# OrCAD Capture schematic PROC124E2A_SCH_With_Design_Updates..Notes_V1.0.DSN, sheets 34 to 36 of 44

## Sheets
34 33. MCU HEADER: size C; title: MCU HEADER
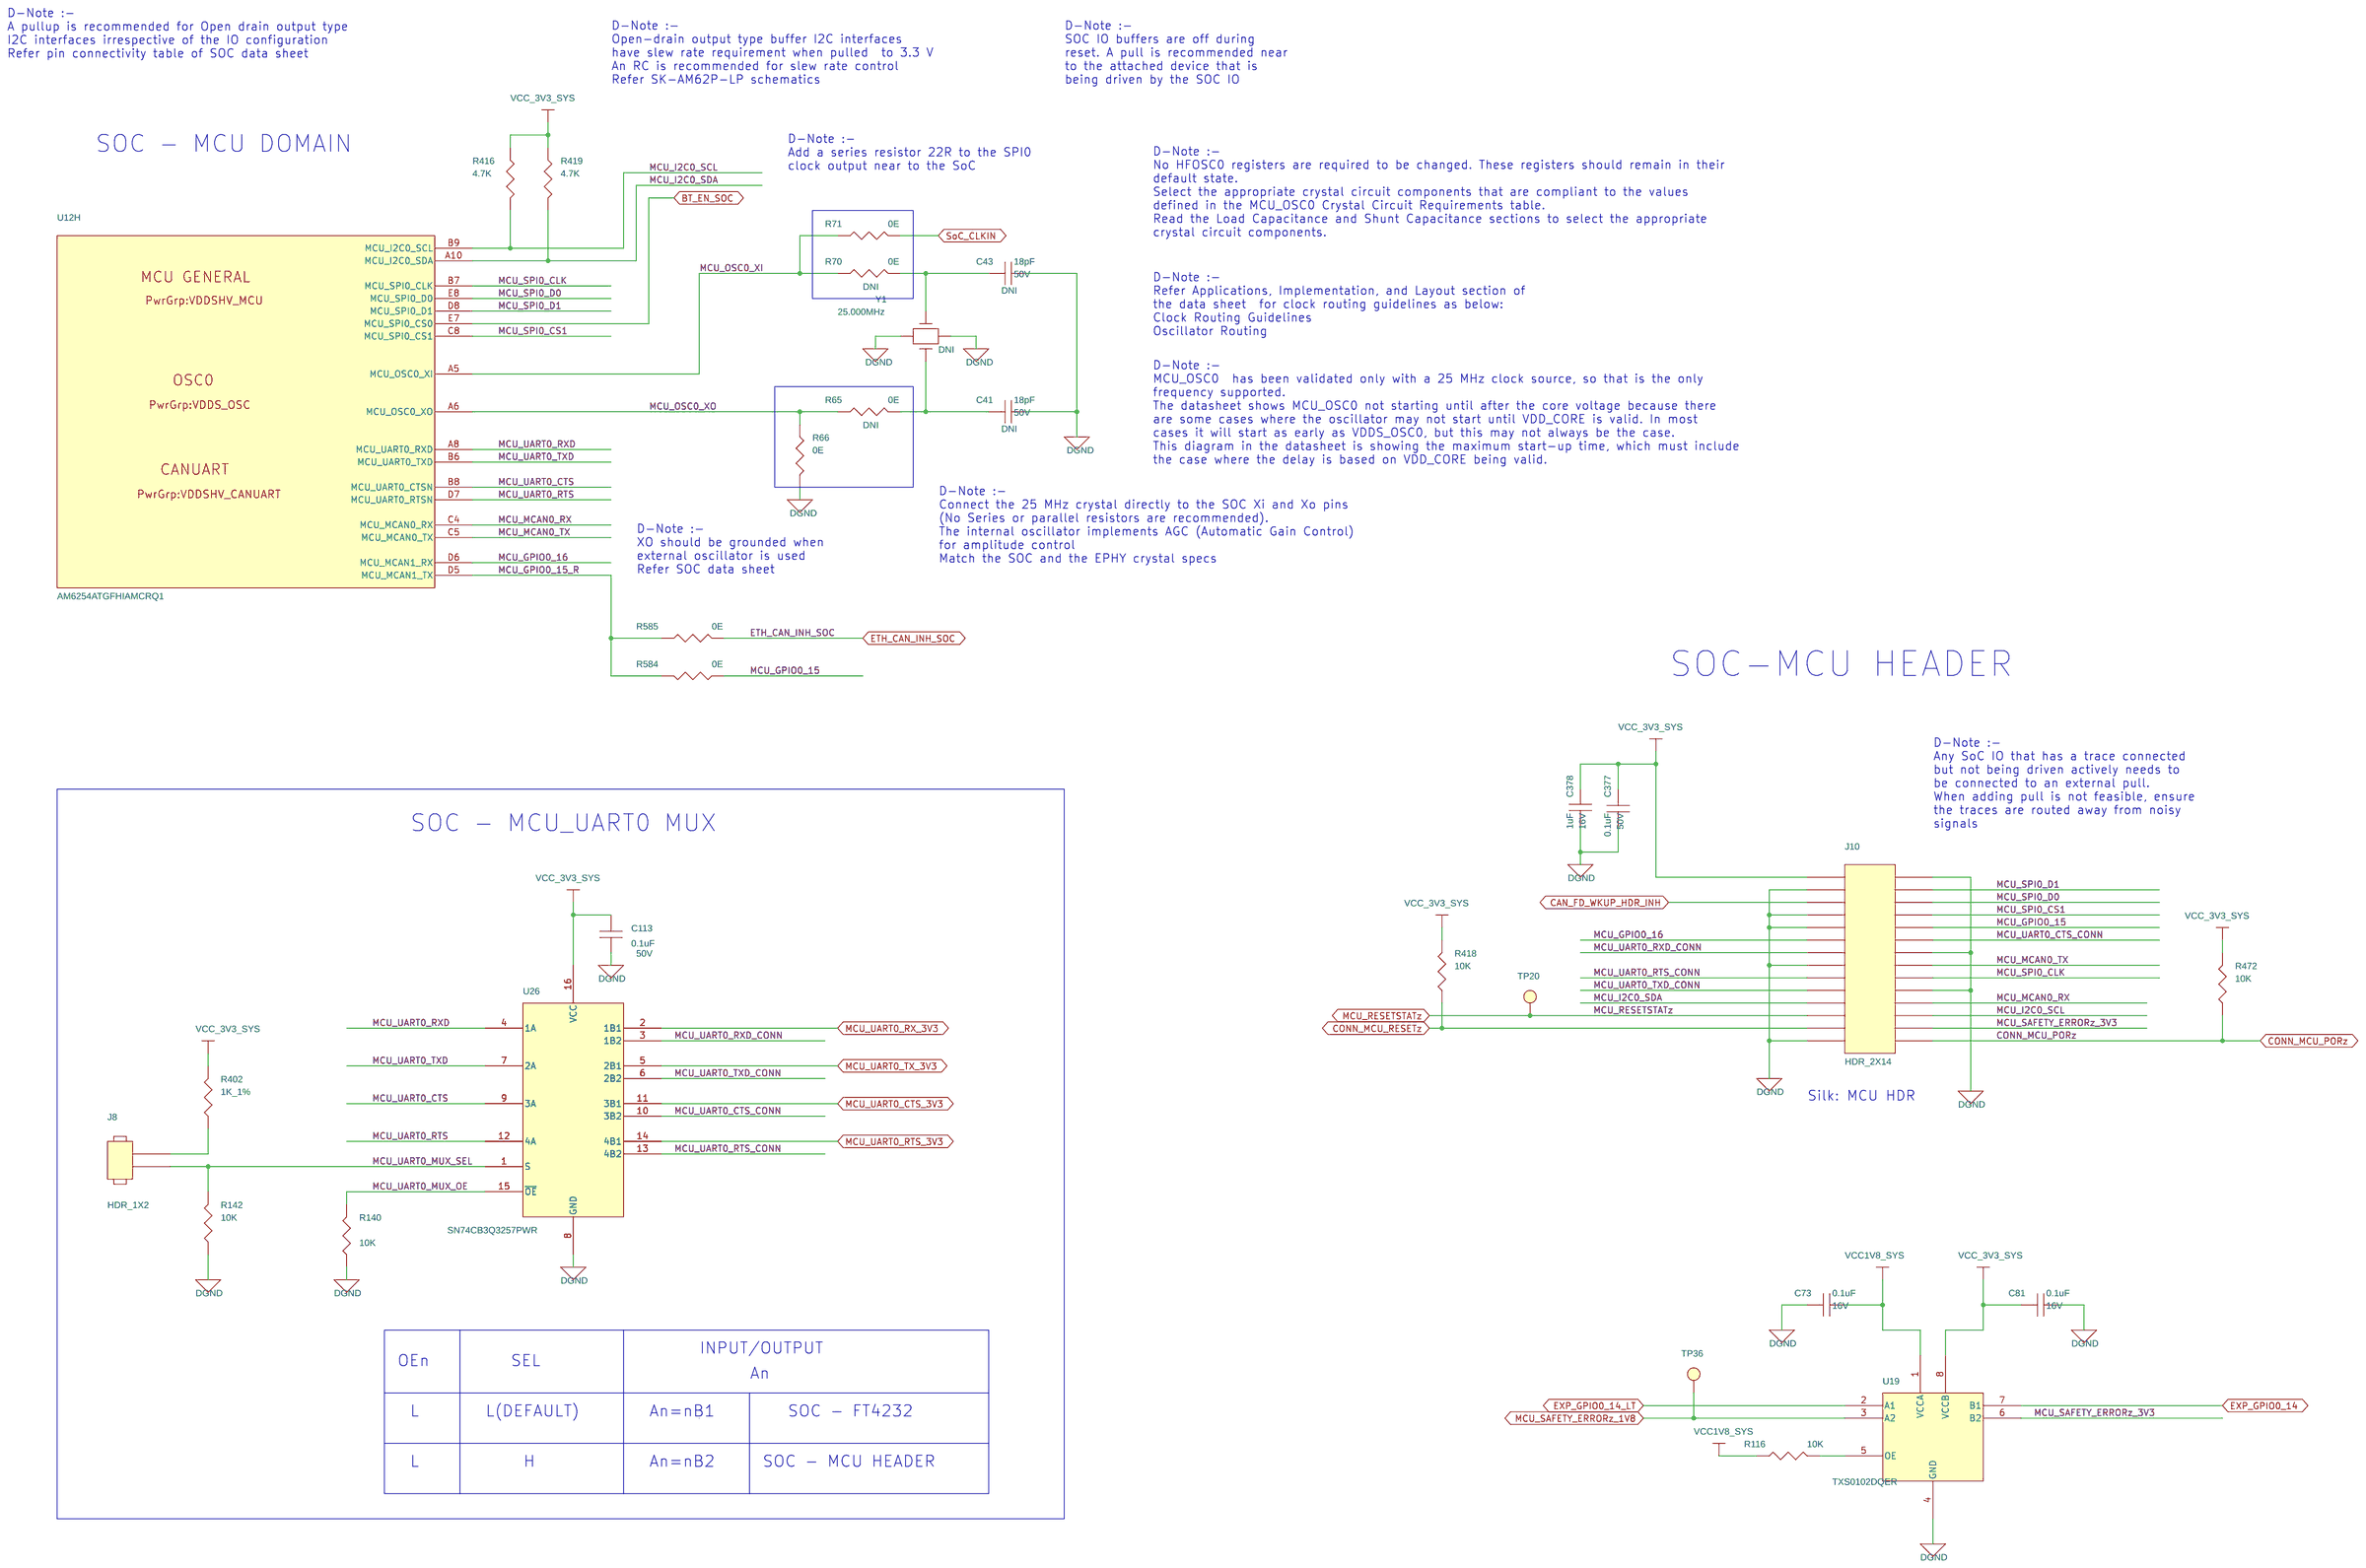
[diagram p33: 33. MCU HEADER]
35 34. USB 2.0 TYPE-A: size B; title: USB 2.0 TYPE-A
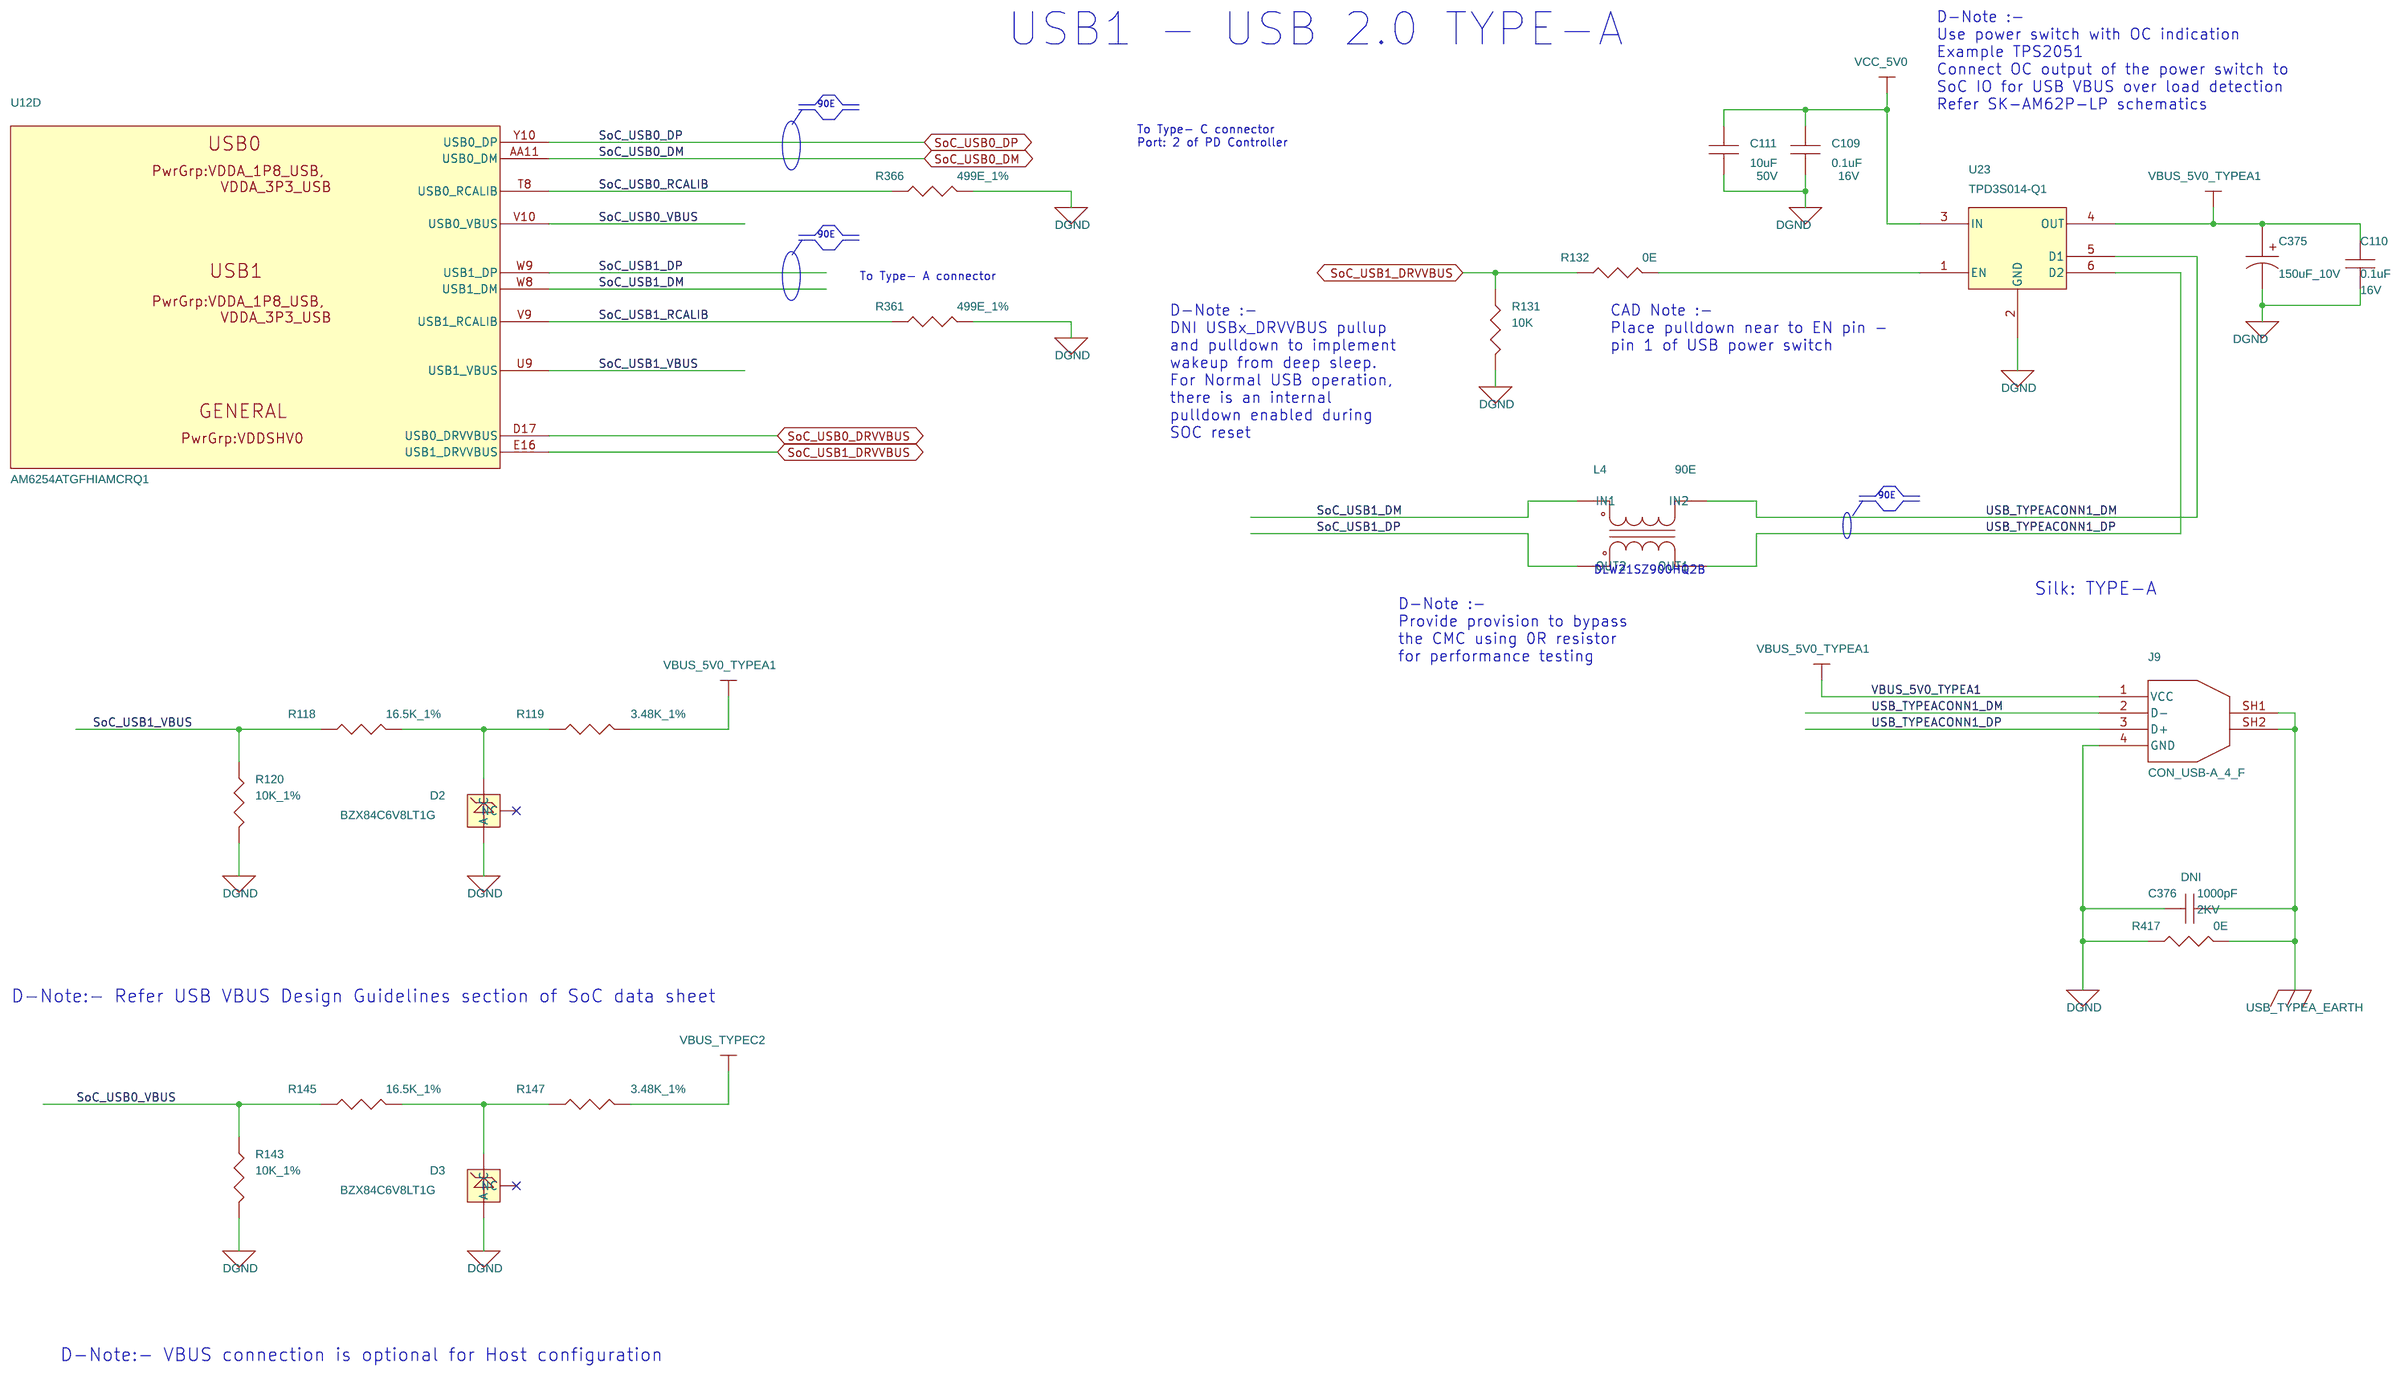
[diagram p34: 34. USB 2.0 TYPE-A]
36 35. USB 2.0 TYPE-C DRP: size C; title: USB TYPE-C DRP
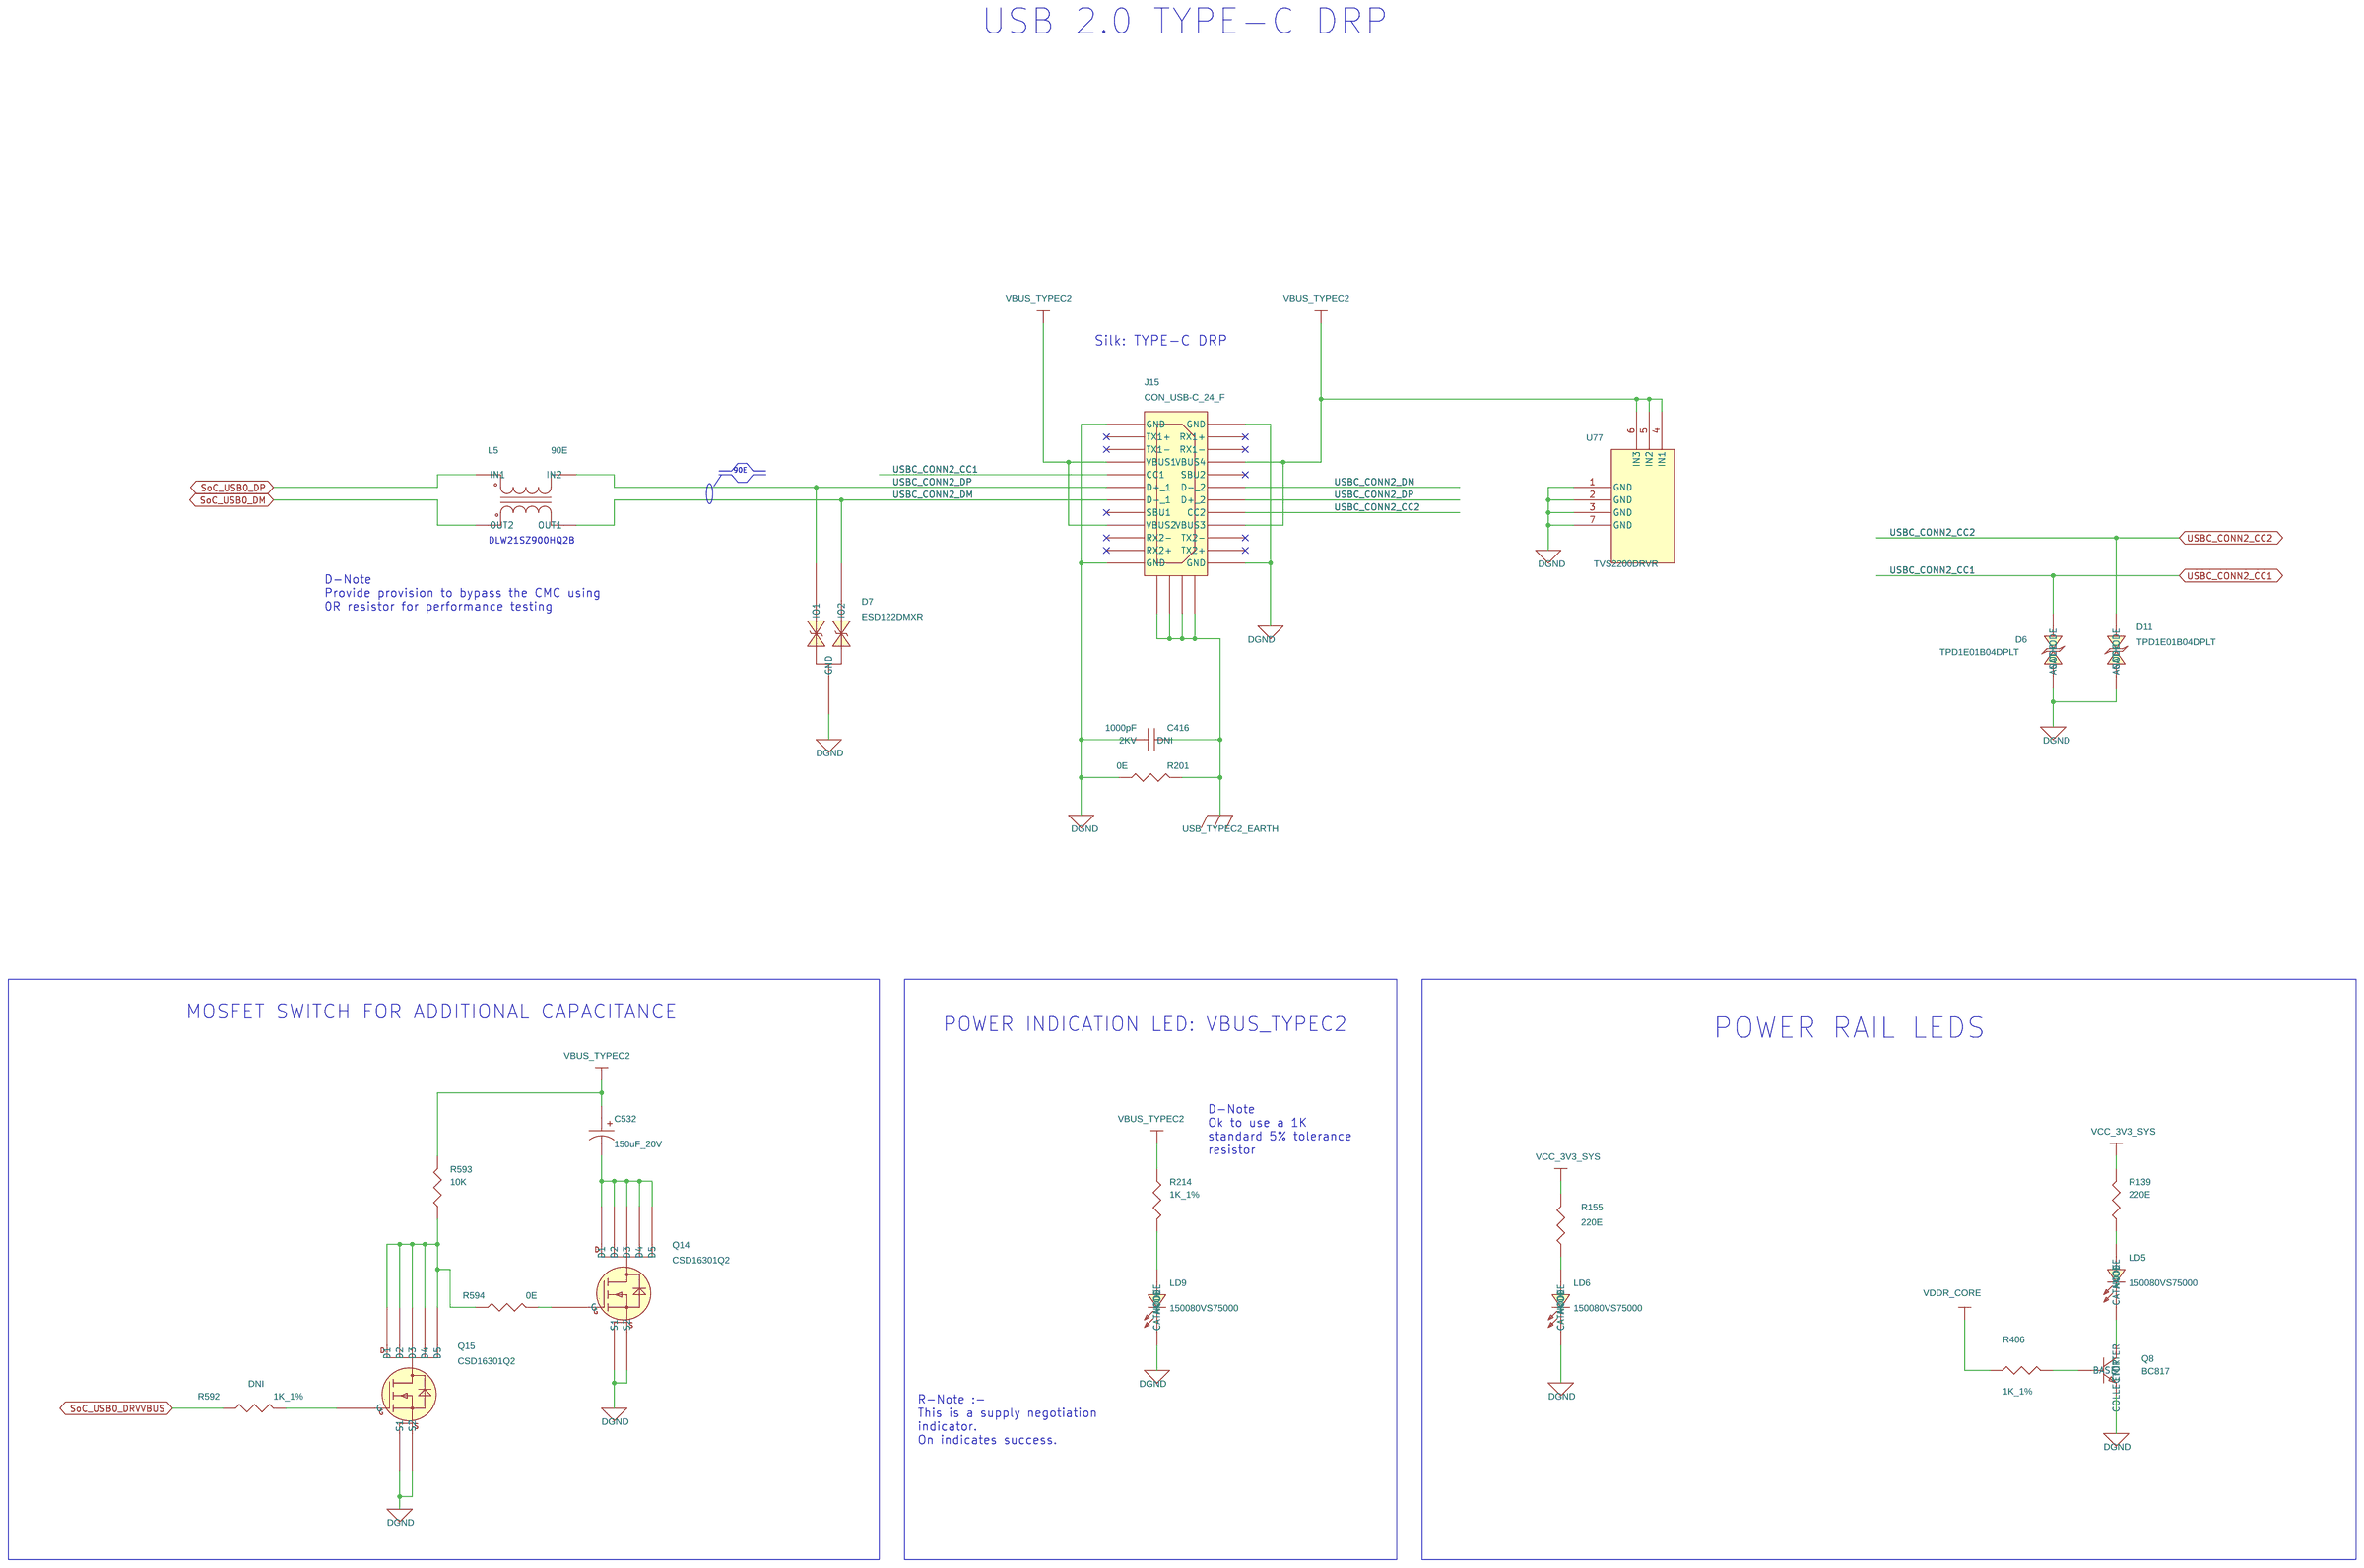
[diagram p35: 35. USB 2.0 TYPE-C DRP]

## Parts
sheet 15. SOC POWER CAPS
U12  AM6254ATGFHIAMCRQ1  [FCBGA441_31-49_680X680_2-6]  (sections A,B,C,D,E,F,G,H,I,J,K,L,M,N,O,P,Q,R)
sheet 33. MCU HEADER
C41  18pF  [CAP0402_0-75]
C43  18pF  [CAP0402_0-75]
C73  0.1uF  [CAP0201_0-5]
C81  0.1uF  [CAP0201_0-5]
C113  0.1uF  [CAP0402_0-75]
C377  0.1uF  [CAP0402_0-75]
C378  1uF  [CAP0201_0-5]
J8  HDR_1X2  [HDR_1X2_90120-0122_S_T_5-6]
J10  HDR_2X14  [HDR_14X2_100_S_T]
R65  0E  [RES0201_0-5]
R66  0E  [RES0201_0-5]
R70  0E  [RES0201_0-5]
R71  0E  [RES0201_0-5]
R116  10K  [RES0201_0-5]
R140  10K  [RES0201_0-5]
R142  10K  [RES0201_0-5]
R402  1K_1%  [RES0201_0-5]
R416  4.7K  [RES0201_0-5]
R418  10K  [RES0201_0-5]
R419  4.7K  [RES0201_0-5]
R472  10K  [RES0201_0-5]
R584  0E  [RES0201_0-5]
R585  0E  [RES0201_0-5]
TP20  TP20_SMD  [TP20_SMD]
TP36  TP20_SMD  [TP20_SMD]
U19  TXS0102DQER  [X2SON8_TXS0102_40X60_0-4]
U26  SN74CB3Q3257PWR  [TSSOP16_25-59_205X180]
Y1  25.000MHz  [XTAL4_XRCGB-FM_80X60_SMD_0-7]
sheet 34. USB 2.0 TYPE-A
C109  0.1uF  [CAP0201_0-5]
C110  0.1uF  [CAP0201_0-5]
C111  10uF  [CAP0805_1-5]
C375  150uF_10V  [CAPT7343D_3-25]
C376  1000pF  [CAP1206_1-75]
D2  BZX84C6V8LT1G  [SOT23-123_1-2]
D3  BZX84C6V8LT1G  [SOT23-123_1-2]
J9  CON_USB-A_4_F  [CON_USBA4_629104151_S_R_S_7-4]
L4  90E  [IND4_DLW21H_90X60_SMD_1-4]
R118  16.5K_1%  [RES0402_0-5]
R119  3.48K_1%  [RES0201_0-5]
R120  10K_1%  [RES0201_0-5]
R131  10K  [RES0201_0-5]
R132  0E  [RES0201_0-5]
R143  10K_1%  [RES0201_0-5]
R145  16.5K_1%  [RES0402_0-5]
R147  3.48K_1%  [RES0201_0-5]
R361  499E_1%  [RES0402_0-5]
R366  499E_1%  [RES0402_0-5]
R417  0E  [RES0603_0-75]
U23  TPD3S014-Q1  [SOT23-6_1-5]
sheet 35. USB 2.0 TYPE-C DRP
C416  1000pF  [CAP1206_1-75]
C532  150uF_20V  [CAPT7343X_4-3]
D6  TPD1E01B04DPLT  [DIO_DFN0201_0-4]
D7  ESD122DMXR  [X2SON3_ESD122DMX_30X40_0-4]
D11  TPD1E01B04DPLT  [DIO_DFN0201_0-4]
J15  CON_USB-C_24_F  [CON_USBC24_2012670_S_R_S_3-9]
L5  90E  [IND4_DLW21H_90X60_SMD_1-4]
LD5  150080VS75000  [LED_150080VS75000_80X50_SMD_0-8]
LD6  150080VS75000  [LED_150080VS75000_80X50_SMD_0-8]
LD9  150080VS75000  [LED_150080VS75000_80X50_SMD_0-8]
Q8  BC817  [TO_SOT23-123]
Q14  CSD16301Q2  [WSON6_CSD13202Q2_80X80_0-8]
Q15  CSD16301Q2  [WSON6_CSD13202Q2_80X80_0-8]
R139  220E  [RES0402_0-5]
R155  220E  [RES0402_0-5]
R201  0E  [RES0603_0-75]
R214  1K_1%  [RES0402_0-5]
R406  1K_1%  [RES0402_0-5]
R592  1K_1%  [RES0201_0-5]
R593  10K  [RES0201_0-5]
R594  0E  [RES0201_0-5]
U77  TVS2200DRVR  [SON6_25-59_85X85_0-8]

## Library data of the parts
U12 = AM6254ATGFHIAMCRQ1_FCBGA441: IC AM62Q SoC MICROPROCESSOR FCBGA441; Chkd/date: PRADEEP/180324; Crtd /date: TAMILARASU/180324; Custom_Duty: 15%; Customs_HS_Code: 85423100; Distributor_name: NA; Distributor_part_number: NA; Footprint Path: Y:\MIS_DATABASE\Library\ALTIUM_TOOL\PCB_FOOTPRINTS\Altium_Footprint_Lib.PcbLib; Height: 2.57MM; Library Path: Y:\MIS_DATABASE\Library\ALTIUM_TOOL\SCHEMATICS_PARTS\MS_MICROPROCESSOR_Library.schlib; Mfr_name: TEXAS INSTRUMENTS; Mistral Part No: 141224030001-R; Package: FCBGA441; Part_type: ICS\DIGITAL\MICROPROCESSOR; Project: TI_AM62Q_BRD; RoHS: NA; Temperature: NA; Tolerance: NA; Voltage: NA; Wattage: NA; Weight: NA; Datasheet: Y:\MIS_DATABASE\DATASHEETS\ICS\DIGITAL\MICROCONTROLLER\AM62Q-SoC.PDF
C41 C43 = CAP: CAP CERAMIC 18pF 50V 5% HI-Q C0G(NP0) 0402; Assembly_Instruction: DNI; Chkd/date: VASANTHA/030315; Crtd /date: NAVEED/271014; Custom_Duty: 15%; Customs_HS_Code: 85322990; Distributor_name: DIGIKEY; Distributor_part_number: 490-3119-1-ND; Footprint Path: Y:\MIS_DATABASE\Library\ALTIUM_TOOL\PCB_FOOTPRINTS\Altium_Footprint_Lib.PcbLib; Height: 0.55MM; Library Path: Y:\MIS_DATABASE\Library\ALTIUM_TOOL\SCHEMATICS_PARTS\MS_DISCRETE_Library.schlib; Mfr_name: MURATA; Mfr_part_number: GJM1555C1H180JB01D; Mistral Part No: 120014100019-R; Package: 0402; Part_type: CAPACITORS\CERAMIC; Project: DC_MIST_RDC; RoHS: RoHS; Temperature: -55°C+125°C; Tolerance: 5%; Voltage: 50V; Wattage: NA; Weight: 6mg; Datasheet: Y:\MIS_DATABASE\DATASHEETS\CAPACITORS\MURATA-GXX-SER_NOV17.PDF
C73 C81 = CAP: CAP CERAMIC 0.1uF 16V 10% X5R 0201; Alt_Mfr_name: YAGEO AMERICA; Alt_Mfr_part_number: CC0402KRX5R8BB104; Chkd/date: MANIRAJA/230118; Crtd /date: MANIRAJA/230118; Custom_Duty: 15%; Customs_HS_Code: 85322990; Distributor_name: DIGIKEY; Distributor_part_number: 490-14305-1-ND; Footprint Path: Y:\MIS_DATABASE\Library\ALTIUM_TOOL\PCB_FOOTPRINTS\Altium_Footprint_Lib.PcbLib; Height: 0.33MM; Library Path: Y:\MIS_DATABASE\Library\ALTIUM_TOOL\SCHEMATICS_PARTS\MS_DISCRETE_Library.schlib; Mfr_name: MURATA; Mfr_part_number: GRM033R61C104KE14D; Mistral Part No: 120009030072-R; Package: 0201; Part_type: CAPACITORS\CERAMIC; Project: TI_MAXIE_CPB; RoHS: RoHS; Temperature: -55°C+85°C; Tolerance: 10%; Voltage: 16V; Wattage: NA; Weight: 0.33mg; Datasheet: Y:\MIS_DATABASE\DATASHEETS\CAPACITORS\GRM033R61C104KE14.PDF
C113 C377 = CAP: CAP CERAMIC 0.1uF 50V 10% X7R 0402; Alt_Mfr_name: YAGEO AMERICA; Alt_Mfr_part_number: CC0402KRX5R8BB104; Chkd/date: MANIRAJA/261020; Crtd /date: ALVY/211020; Custom_Duty: 15%; Customs_HS_Code: 85322990; Distributor_name: DIGIKEY; Distributor_part_number: 490-10700-1-ND; Footprint Path: Y:\MIS_DATABASE\Library\ALTIUM_TOOL\PCB_FOOTPRINTS\Altium_Footprint_Lib.PcbLib; Height: 0.55MM; Library Path: Y:\MIS_DATABASE\Library\ALTIUM_TOOL\SCHEMATICS_PARTS\MS_DISCRETE_Library.schlib; Mfr_name: MURATA; Mfr_part_number: GRM155R71H104KE14D; Mistral Part No: 120011100014-R; Package: 0402; Part_type: CAPACITORS\CERAMIC; Project: J7_CP; RoHS: RoHS; Temperature: -55°C+125°C; Tolerance: 10%; Voltage: 50V; Wattage: NA; Weight: 3.1mg; Datasheet: Y:\MIS_DATABASE\DATASHEETS\CAPACITORS\GRM155R71H104KE14.PDF
C378 = CAP: CAP CERAMIC 1uF 16V 20% X5R 0201; Chkd/date: MANIRAJA/300520; Crtd /date: ALVY/260520; Custom_Duty: 15%; Customs_HS_Code: 85322990; Distributor_name: DIGIKEY; Distributor_part_number: 490-18654-1-ND; Footprint Path: Y:\MIS_DATABASE\Library\ALTIUM_TOOL\PCB_FOOTPRINTS\Altium_Footprint_Lib.PcbLib; Height: 0.39MM; Library Path: Y:\MIS_DATABASE\Library\ALTIUM_TOOL\SCHEMATICS_PARTS\MS_DISCRETE_Library.schlib; Mfr_name: MURATA; Mfr_part_number: GRM033R61C105ME15D; Mistral Part No: 120018090038-R; Package: 0201; Part_type: CAPACITORS\CERAMIC; Project: QCS610_NANOSOM; RoHS: RoHS; Temperature: -55°C+85°C; Tolerance: 20%; Voltage: 16V; Wattage: NA; Weight: 0.33mg; Datasheet: Y:\MIS_DATABASE\DATASHEETS\CAPACITORS\GRM033R61C105ME15.PDF
J8 = HEADER_2X1: CON HDR 1X2 2.54MM PITCH ST TH; Chkd/date: NAVEED/210714; Crtd /date: USMAN/031012; Custom_Duty: 24%; Customs_HS_Code: 85369090; Distributor_name: DIGIKEY; Distributor_part_number: WM8072-ND; Footprint Path: Y:\MIS_DATABASE\Library\ALTIUM_TOOL\PCB_FOOTPRINTS\Altium_Footprint_Lib.PcbLib; Height: 5.60MM; Library Path: Y:\MIS_DATABASE\Library\ALTIUM_TOOL\SCHEMATICS_PARTS\MS_CONNECTOR_Library.schlib; Mfr_name: MOLEX; Mfr_part_number: 90120-0122; Mistral Part No: 150012100005-R; Package: THRU-HOLE; Part_type: CONNECTOR\HEADERS; Project: NPOL_FEP; RoHS: RoHS; Temperature: -55°C+125°C; Tolerance: NA; Voltage: NA; Wattage: NA; Weight: 122mg; Datasheet: Y:\MIS_DATABASE\DATASHEETS\CONNECTORS\90120-XX.PDF
J10 = HEADER_14x2: CON HDR 2X14 2.54MM PITCH ST TH; Chkd/date: NAVEED/280515; Crtd /date: VASANTHA/111114; Custom_Duty: 0.24; Customs_HS_Code: 85369090; Distributor_name: DIGIKEY; Distributor_part_number: S2012EC-14-ND; Height: 8.34MM; Mfr_name: SULLINS; Mfr_part_number: PREC014DAAN-RC; Mistral Part No: 150014110005-R; Package: THRU-HOLE; Part_type: CONNECTOR\HEADERS; Project: GALILEO_EVM; RoHS: RoHS; Temperature: -40°C+105°C; Tolerance: NA; Voltage: NA; Wattage: NA; Weight: NA; Datasheet: Y:\MIS_DATABASE\DATASHEETS\CONNECTORS\PRXXXN-RC.PDF
R65 R70 = RESISTOR: RES 0E 1/20W 5% 0201; Assembly_Instruction: DNI; Chkd/date: NAVEED/301214; Crtd /date: MUDDU/120710; Custom_Duty: 15%; Customs_HS_Code: 85332119; Distributor_name: DIGIKEY; Distributor_part_number: 311-0.0NCT-ND; Footprint Path: Y:\MIS_DATABASE\Library\ALTIUM_TOOL\PCB_FOOTPRINTS\Altium_Footprint_Lib.PcbLib; Height: 0.26MM; Library Path: Y:\MIS_DATABASE\Library\ALTIUM_TOOL\SCHEMATICS_PARTS\MS_DISCRETE_Library.schlib; Mfr_name: YAGEO AMERICA; Mfr_part_number: RC0201JR-070RL; Mistral Part No: 110010070067-R; Package: 0201; Part_type: RESISTORS\FIXED; Project: PB_BUGBASE; RoHS: RoHS; Temperature: -55°C+125°C; Tolerance: 5%; Voltage: NA; Wattage: 1/20W; Weight: 0.17mg; Datasheet: Y:\MIS_DATABASE\DATASHEETS\RESISTORS\RCXXXXL-SER_MAR18.PDF
R66 R71 R132 R584 R585 R594 = RESISTOR: RES 0E 1/20W 5% 0201; Chkd/date: NAVEED/301214; Crtd /date: MUDDU/120710; Custom_Duty: 15%; Customs_HS_Code: 85332119; Distributor_name: DIGIKEY; Distributor_part_number: 311-0.0NCT-ND; Footprint Path: Y:\MIS_DATABASE\Library\ALTIUM_TOOL\PCB_FOOTPRINTS\Altium_Footprint_Lib.PcbLib; Height: 0.26MM; Library Path: Y:\MIS_DATABASE\Library\ALTIUM_TOOL\SCHEMATICS_PARTS\MS_DISCRETE_Library.schlib; Mfr_name: YAGEO AMERICA; Mfr_part_number: RC0201JR-070RL; Mistral Part No: 110010070067-R; Package: 0201; Part_type: RESISTORS\FIXED; Project: PB_BUGBASE; RoHS: RoHS; Temperature: -55°C+125°C; Tolerance: 5%; Voltage: NA; Wattage: 1/20W; Weight: 0.17mg; Datasheet: Y:\MIS_DATABASE\DATASHEETS\RESISTORS\RCXXXXL-SER_MAR18.PDF
R116 R131 R140 R142 R418 R472 R593 = RESISTOR: RES 10K 1/20W 5% 0201; Chkd/date: MANIRAJA/050517; Crtd /date: MANIRAJA/050517; Custom_Duty: 15%; Customs_HS_Code: 85332119; Distributor_name: DIGIKEY; Distributor_part_number: 311-10KNCT-ND; Footprint Path: Y:\MIS_DATABASE\Library\ALTIUM_TOOL\PCB_FOOTPRINTS\Altium_Footprint_Lib.PcbLib; Height: 0.26MM; Library Path: Y:\MIS_DATABASE\Library\ALTIUM_TOOL\SCHEMATICS_PARTS\MS_DISCRETE_Library.schlib; Mfr_name: YAGEO AMERICA; Mfr_part_number: RC0201JR-0710KL; Mistral Part No: 110010070051-R; Package: 0201; Part_type: RESISTORS\FIXED; Project: GOLDEN-I LITE; RoHS: RoHS; Temperature: -55°C+125°C; Tolerance: 5%; Voltage: NA; Wattage: 1/20W; Weight: 0.17mg; Datasheet: Y:\MIS_DATABASE\DATASHEETS\RESISTORS\RCXXXXL-SER_MAR18.PDF
R402 = RESISTOR: RES 1K 1/20W 1% 0201; Chkd/date: JEBRAN/110815; Crtd /date: JEBRAN/110815; Custom_Duty: 15%; Customs_HS_Code: 85332119; Distributor_name: DIGIKEY; Distributor_part_number: 541-1.00KAABCT-ND; Footprint Path: Y:\MIS_DATABASE\Library\ALTIUM_TOOL\PCB_FOOTPRINTS\Altium_Footprint_Lib.PcbLib; Height: 0.28MM; Library Path: Y:\MIS_DATABASE\Library\ALTIUM_TOOL\SCHEMATICS_PARTS\MS_DISCRETE_Library.schlib; Mfr_name: VISHAY; Mfr_part_number: CRCW02011K00FKED; Mistral Part No: 110015080014-R; Package: 0201; Part_type: RESISTORS\FIXED; Project: OCTASIC_3000; RoHS: RoHS; Temperature: -55°C+155°C; Tolerance: 1%; Voltage: NA; Wattage: 1/20W; Weight: 0.17mg; Datasheet: Y:\MIS_DATABASE\DATASHEETS\RESISTORS\CRCW0201.PDF
R416 R419 = RESISTOR: RES 4.7K 1/20W 5% 0201; Chkd/date: MANIRAJA/200921; Crtd /date: ALVY/200921; Custom_Duty: 15%; Customs_HS_Code: 85332119; Distributor_name: DIGIKEY; Distributor_part_number: 311-4.7KNCT-ND; Footprint Path: Y:\MIS_DATABASE\Library\ALTIUM_TOOL\PCB_FOOTPRINTS\Altium_Footprint_Lib.PcbLib; Height: 0.26MM; Library Path: Y:\MIS_DATABASE\Library\ALTIUM_TOOL\SCHEMATICS_PARTS\MS_DISCRETE_Library.schlib; Mfr_name: YAGEO AMERICA; Mfr_part_number: RC0201JR-074K7L; Mistral Part No: 110021090007-R; Package: 0201; Part_type: RESISTORS\FIXED; Project: TI_AM62x SKEVM_BRD; RoHS: RoHS; Temperature: -55°C+125°C; Tolerance: 5%; Voltage: NA; Wattage: 1/20W; Weight: 0.17mg; Datasheet: Y:\MIS_DATABASE\DATASHEETS\RESISTORS\RCXXXXL-SER_MAR18.PDF
TP20 TP36 = TESTPOINT: TESTPOINT CIR 20 SMD; Chkd/date: SHREESHAIL/171006; Crtd /date: MAZHAR/171006; Custom_Duty: NA; Customs_HS_Code: NA; Distributor_name: NA; Distributor_part_number: NA; Footprint Path: Y:\MIS_DATABASE\Library\ALTIUM_TOOL\PCB_FOOTPRINTS\Altium_Footprint_Lib.PcbLib; Height: NA; Library Path: Y:\MIS_DATABASE\Library\ALTIUM_TOOL\SCHEMATICS_PARTS\MS_DISCRETE_Library.schlib; MECHANICAL 3D STEP FILE: NA; Mfr_name: LOCAL; Mistral Part No: NA; Package: SMD; Project: BT MODULE_CSRBC04; RoHS: NA; Temperature: NA; Tolerance: NA; Voltage: NA; Wattage: NA; Weight: NA; Datasheet: NA
U19 = TXS0102DQX_SON8: IC 2-BIT BI-DIR VOLTAGE-LEVEL TRANSLATOR FOR OPEN-DRAIN AND PUSH-PULL X2SON8; Chkd/date: MANIRAJA/010719; Crtd /date: CHAITHANYA230512; Custom_Duty: 15%; Customs_HS_Code: 85423100; Distributor_name: DIGIKEY; Distributor_part_number: 296-28368-1-ND; Footprint Path: Y:\MIS_DATABASE\Library\ALTIUM_TOOL\PCB_FOOTPRINTS\Altium_Footprint_Lib.PcbLib; Height: 0.40MM; Library Path: Y:\MIS_DATABASE\Library\ALTIUM_TOOL\SCHEMATICS_PARTS\MS_MISCINTERFACE_Library.schlib; Mfr_name: TEXAS INSTRUMENTS; Mistral Part No: 141012050010-R; Package: X2SON8; Part_type: ICS\INTERFACE\LEVEL TRANSLATOR; Project: GEN_3-8_DB; RoHS: RoHS; Temperature: -40°C+85°C; Tolerance: NA; Voltage: NA; Wattage: NA; Weight: 1.2mg; Datasheet: Y:\MIS_DATABASE\DATASHEETS\ICS\INTERFACE\TXS0102-SER.PDF
U26 = SN74CB3Q3257PWR_TSSOP16: IC 4BIT 1-OF-2 FET MULTIPLEXER/DEMULTIPLEXER TSSOP16; Chkd/date: SUHAS/251010; Crtd /date: USMAN/060109; Custom_Duty: 15%; Customs_HS_Code: 85423100; Distributor_name: DIGIKEY; Distributor_part_number: 296-19138-1-ND; Footprint Path: Y:\MIS_DATABASE\Library\ALTIUM_TOOL\PCB_FOOTPRINTS\Altium_Footprint_Lib.PcbLib; Footprint Ref: TSSOP16_25-59_205X180_1-2; Height: 1.20MM; Library Path: Y:\MIS_DATABASE\Library\ALTIUM_TOOL\SCHEMATICS_PARTS\MS_COMBINATIONAL_Library.schlib; MECHANICAL 3D STEP FILE: TSSOP16_25-59_205X180_1-2; Mfr_name: TEXAS INSTRUMENTS; Mistral Part No: 141009030117-R; Package: TSSOP16; Part_type: ICS\DIGITAL\COMBINATIONAL; Project: OMAP_EVM; RoHS: Sb/ Br FREE; Temperature: -40°C+85°C; Datasheet: Y:\MIS_DATABASE\DATASHEETS\ICS\DIGITAL\COMBINATIONAL\SN74CB3Q3257.PDF
Y1 = CRY4_13: CRY 25.000MHz 6pF SMD; Assembly_Instruction: DNI; Chkd/date: MANIRAJA/151020; Crtd /date: ALVY/151020; Custom_Duty: 24%; Customs_HS_Code: 85439000; Distributor_name: DIGIKEY; Distributor_part_number: 490-5578-1-ND; Footprint Path: Y:\MIS_DATABASE\Library\ALTIUM_TOOL\PCB_FOOTPRINTS\Altium_Footprint_Lib.PcbLib; Height: 0.70MM; Library Path: Y:\MIS_DATABASE\Library\ALTIUM_TOOL\SCHEMATICS_PARTS\MS_DISCRETE_Library.schlib; Mfr_name: MURATA; Mfr_part_number: XRCGB25M000F3M00R0; Mistral Part No: 130020100043-R; Package: SMD; Part_type: CRYSTAL; Project: AM64X_SKEVM; RoHS: RoHS; Temperature: -30°C+85°C; Tolerance: NA; Voltage: NA; Wattage: NA; Weight: 23mg; Datasheet: Y:\MIS_DATABASE\DATASHEETS\MISC\CRY_OSC\XRCGB.PDF
C109 C110 = CAP: CAP CERAMIC 0.1uF 16V 10% X5R 0201; Chkd/date: MANIRAJA/230118; Crtd /date: MANIRAJA/230118; Custom_Duty: 15%; Customs_HS_Code: 85322990; Distributor_name: DIGIKEY; Distributor_part_number: 490-14305-1-ND; Footprint Path: Y:\MIS_DATABASE\Library\ALTIUM_TOOL\PCB_FOOTPRINTS\Altium_Footprint_Lib.PcbLib; Height: 0.33MM; Library Path: Y:\MIS_DATABASE\Library\ALTIUM_TOOL\SCHEMATICS_PARTS\MS_DISCRETE_Library.schlib; Mfr_name: MURATA; Mfr_part_number: GRM033R61C104KE14D; Mistral Part No: 120009030072-R; Package: 0201; Part_type: CAPACITORS\CERAMIC; Project: TI_MAXIE_CPB; RoHS: RoHS; Temperature: -55°C+85°C; Tolerance: 10%; Voltage: 16V; Wattage: NA; Weight: 0.33mg; Datasheet: Y:\MIS_DATABASE\DATASHEETS\CAPACITORS\GRM033R61C104KE14.PDF
C111 = CAP: CAP CERAMIC 10uF 50V 10% X5R 0805; Chkd/date: MANIRAJA/010321; Crtd /date: ALVY/010321; Custom_Duty: 15%; Customs_HS_Code: 85322990; Distributor_name: DIGIKEY; Distributor_part_number: 490-18663-1-ND; Footprint Path: Y:\MIS_DATABASE\Library\ALTIUM_TOOL\PCB_FOOTPRINTS\Altium_Footprint_Lib.PcbLib; Height: 1.45MM; Library Path: Y:\MIS_DATABASE\Library\ALTIUM_TOOL\SCHEMATICS_PARTS\MS_DISCRETE_Library.schlib; Mfr_name: MURATA; Mfr_part_number: GRM21BR61H106KE43L; Mistral Part No: 120021030002-R; Package: 0805; Part_type: CAPACITORS\CERAMIC; Project: J7ES_SK_BRD; RoHS: RoHS; Temperature: -55°C+85°C; Tolerance: 10%; Voltage: 50V; Wattage: NA; Weight: 6.4mg; Datasheet: Y:\MIS_DATABASE\DATASHEETS\CAPACITORS\GRM21BR61H106KE43.PDF
C375 = CAP_POL: CAP TANTALUM 150uF 10V 10% ESR 600mE D7343; Chkd/date: ALVY/200921; Crtd /date: MANIRAJA/200921; Custom_Duty: 15%; Customs_HS_Code: 85322990; Distributor_name: DIGIKEY; Distributor_part_number: 718-1960-1-ND; Footprint Path: Y:\MIS_DATABASE\Library\ALTIUM_TOOL\PCB_FOOTPRINTS\Altium_Footprint_Lib.PcbLib; Height: 3.10MM; Library Path: Y:\MIS_DATABASE\Library\ALTIUM_TOOL\SCHEMATICS_PARTS\MS_DISCRETE_Library.schlib; Mfr_name: VISHAY; Mfr_part_number: 293D157X9010D2TE3; Mistral Part No: 120021090007-R; Package: D7343; Part_type: CAPACITORS\TANTALUM; Project: TI_AM62x SKEVM_BRD; RoHS: RoHS; Temperature: -55°C+125°C; Tolerance: 10%; Voltage: 10V; Wattage: NA; Weight: 400mg; Datasheet: Y:\MIS_DATABASE\DATASHEETS\CAPACITORS\293D_SER_MAR20.PDF
C376 C416 = CAP: CAP CERAMIC 1000pF 2KV 10% X7R 1206; Assembly_Instruction: DNI; Chkd/date: SHREESHAIL/291106; Crtd /date: MAZHAR/281106; Custom_Duty: 15%; Customs_HS_Code: 85322990; Distributor_name: DIGIKEY; Distributor_part_number: 478-2956-1-ND; Footprint Path: Y:\MIS_DATABASE\Library\ALTIUM_TOOL\PCB_FOOTPRINTS\Altium_Footprint_Lib.PcbLib; Height: 1.52MM; Library Path: Y:\MIS_DATABASE\Library\ALTIUM_TOOL\SCHEMATICS_PARTS\MS_DISCRETE_Library.schlib; Mfr_name: AVX CORPORATION; Mfr_part_number: 1206GC102KAT1A; Mistral Part No: 120015080006-R; Package: 1206; Part_type: CAPACITORS\CERAMIC; Project: ADR1B; RoHS: RoHS; Temperature: -55°C+125°C; Tolerance: 10%; Voltage: 2KV; Wattage: NA; Weight: 16.2mg; Datasheet: Y:\MIS_DATABASE\DATASHEETS\CAPACITORS\AVX_HV-MLC.PDF
D2 D3 = DIODE_ZENER_SOT23_13: DIODE ZENER 250mW 6.8V SOT23-123; Chkd/date: MANIRAJA/031017; Crtd /date: MANIRAJA/031017; Custom_Duty: 15%; Customs_HS_Code: 85412900; Distributor_name: DIGIKEY; Distributor_part_number: BZX84C6V8LT1GOSCT-ND; Height: 1.11MM; Mfr_name: ON SEMICONDUCTOR; Mistral Part No: 130017100002-R; Package: SOT23-123; Part_type: DIODE\ZENER; Project: TI_MAXIE_CPB; RoHS: RoHS; Temperature: -65°C+150°C; Tolerance: NA; Voltage: 6.8V; Wattage: NA; Weight: 8mg; Datasheet: Y:\MIS_DATABASE\DATASHEETS\DISCRETES\DIODES\BZX84XX.PDF
J9 = CON_USB-A_4_2SH: CON USB-A TYPE 4POS FEMALE RT SMD; Chkd/date: MANIRAJA/271017; Crtd /date: MANIRAJA/271017; Custom_Duty: 24%; Customs_HS_Code: 85369090; Distributor_name: DIGIKEY; Distributor_part_number: 732-5969-1-ND; Height: 7.35MM; Manufacturer: WURTH ELECTRONICS; Mfr_name: WURTH ELECTRONICS; Mfr_part_number: 629104151021; Mistral Part No: 150017100042-R; Package: SMD; Part_type: CONNECTOR\USB; Project: TI_SVB_MAXWELL_SPM; RoHS: RoHS; Temperature: -40°C+85°C; Tolerance: NA; Voltage: NA; Wattage: NA; Weight: NA; Datasheet: Y:\MIS_DATABASE\DATASHEETS\CONNECTORS\629104151021.PDF
L4 L5 = INDUCTOR_DLW31S: IND COMMON MODE CHOKE 90E 280mA SMD; Chkd/date: MANIRAJA/270619; Crtd /date: MANIRAJA/270619; Custom_Duty: 24%; Customs_HS_Code: 85437099; Distributor_name: NA; Distributor_part_number: NA; Footprint Path: Y:\MIS_DATABASE\Library\ALTIUM_TOOL\PCB_FOOTPRINTS\Altium_Footprint_Lib.PcbLib; Height: 1.40MM; Library Path: Y:\MIS_DATABASE\Library\ALTIUM_TOOL\SCHEMATICS_PARTS\MS_DISCRETE_Library.schlib; Mfr_name: MURATA; Mfr_part_number: DLW21SZ900HQ2B; Mistral Part No: 130019060035-R; Package: SMD; Part_type: INDUCTOR; Project: TI_J7ES_CP; RoHS: RoHS; Temperature: -40°C+105°C; Tolerance: NA; Voltage: NA; Wattage: NA; Weight: 11mg; Datasheet: Y:\MIS_DATABASE\DATASHEETS\DISCRETES\INDUCTORS\DLW21SZ900HQ2B.PDF
R118 R145 = RESISTOR: RES 16.5K 1/16W 1% 0402; Chkd/date: ALVY/091220; Crtd /date: MANIRAJA/091220; Custom_Duty: 15%; Customs_HS_Code: 85332119; Distributor_name: DIGIKEY; Distributor_part_number: YAG3002CT-ND; Footprint Path: Y:\MIS_DATABASE\Library\ALTIUM_TOOL\PCB_FOOTPRINTS\Altium_Footprint_Lib.PcbLib; Height: 0.40MM; Library Path: Y:\MIS_DATABASE\Library\ALTIUM_TOOL\SCHEMATICS_PARTS\MS_DISCRETE_Library.schlib; Mfr_name: YAGEO AMERICA; Mfr_part_number: RC0402FR-0716K5L; Mistral Part No: 110020120011-R; Package: 0402; Part_type: RESISTORS\FIXED; Project: TI_AM243x LP EVM; RoHS: RoHS; Temperature: -55°C+155°C; Tolerance: 1%; Voltage: NA; Wattage: 1/16W; Weight: 0.65mg; Datasheet: Y:\MIS_DATABASE\DATASHEETS\RESISTORS\RCXXXXL-SER_MAR18.PDF
R119 R147 = RESISTOR: RES 3.48K 1/20W 1% 0201; Chkd/date: PRADEEP/281123; Crtd /date: TAMILARASU/071123; Custom_Duty: 15%; Customs_HS_Code: 85322990; Distributor_name: DIGIKEY; Distributor_part_number: P122951CT-ND; Footprint Path: Y:\MIS_DATABASE\Library\ALTIUM_TOOL\PCB_FOOTPRINTS\Altium_Footprint_Lib.PcbLib; Height: 0.26MM; Library Path: Y:\MIS_DATABASE\Library\ALTIUM_TOOL\SCHEMATICS_PARTS\MS_DISCRETE_Library.schlib; Mfr_name: PANASONIC-ECG; Mfr_part_number: ERJ-1GNF3481C; Mistral Part No: 110023110006-R; Package: 0201; Part_type: RESISTORS\FIXED; Project: AM62P SK; RoHS: RoHS; Temperature: -55°C+125°C; Tolerance: 0.01; Voltage: NA; Wattage: 1/20W; Weight: 0.15mg; Datasheet: Y:\MIS_DATABASE\DATASHEETS\RESISTORS\PAN-ERJSER_DEC22.PDF
R120 R143 = RESISTOR: RES 10K 1/20W 1% 0201; Chkd/date: VASANTHA/270117; Crtd /date: MANIRAJA/270117; Custom_Duty: 15%; Customs_HS_Code: 85332119; Distributor_name: DIGIKEY; Distributor_part_number: 311-10.0KMCT-ND; Footprint Path: Y:\MIS_DATABASE\Library\ALTIUM_TOOL\PCB_FOOTPRINTS\Altium_Footprint_Lib.PcbLib; Height: 0.26MM; Library Path: Y:\MIS_DATABASE\Library\ALTIUM_TOOL\SCHEMATICS_PARTS\MS_DISCRETE_Library.schlib; Mfr_name: YAGEO AMERICA; Mfr_part_number: RC0201FR-0710KL; Mistral Part No: 110011040018-R; Package: 0201; Part_type: RESISTORS\FIXED; Project: GOLDEN-I LITE; RoHS: RoHS; Temperature: -55°C+125°C; Tolerance: 1%; Voltage: NA; Wattage: 1/20W; Weight: 0.17mg; Datasheet: Y:\MIS_DATABASE\DATASHEETS\RESISTORS\RCXXXXL-SER_MAR18.PDF
R361 R366 = RESISTOR: RES 499E 1/16W 1% 0402; Chkd/date: MANIRAJA/051020; Crtd /date: ALVY/051020; Custom_Duty: 15%; Customs_HS_Code: 85332119; Distributor_name: DIGIKEY; Distributor_part_number: 311-499LRCT-ND; Footprint Path: Y:\MIS_DATABASE\Library\ALTIUM_TOOL\PCB_FOOTPRINTS\Altium_Footprint_Lib.PcbLib; Height: 0.40MM; Library Path: Y:\MIS_DATABASE\Library\ALTIUM_TOOL\SCHEMATICS_PARTS\MS_DISCRETE_Library.schlib; Mfr_name: YAGEO AMERICA; Mfr_part_number: RC0402FR-07499RL; Mistral Part No: 110020080006-R; Package: 0402; Part_type: RESISTORS\FIXED; Project: AM64XX_EVM; RoHS: RoHS; Temperature: -55°C+155°C; Tolerance: 1%; Voltage: NA; Wattage: 1/16W; Weight: 0.65mg; Datasheet: Y:\MIS_DATABASE\DATASHEETS\RESISTORS\RCXXXXL-SER_MAR18.PDF
R201 R417 = RESISTOR: RES 0E 1/10W 5% 0603; Chkd/date: MANIRAJA/051217; Crtd /date: BAVISH/180211; Custom_Duty: 15%; Customs_HS_Code: 85332119; Distributor_name: DIGIKEY; Distributor_part_number: 311-0.0GRCT-ND; Footprint Path: Y:\MIS_DATABASE\Library\ALTIUM_TOOL\PCB_FOOTPRINTS\Altium_Footprint_Lib.PcbLib; Height: 0.55MM; Library Path: Y:\MIS_DATABASE\Library\ALTIUM_TOOL\SCHEMATICS_PARTS\MS_DISCRETE_Library.schlib; Mfr_name: YAGEO AMERICA; Mfr_part_number: RC0603JR-070RL; Mistral Part No: 110011020013-R; Package: 0603; Part_type: RESISTORS\FIXED; Project: KENNEL; RoHS: RoHS; Temperature: -55°C+155°C; Tolerance: 5%; Voltage: NA; Wattage: 1/10W; Weight: 2mg; Datasheet: Y:\MIS_DATABASE\DATASHEETS\RESISTORS\RCXXXXL-SER_MAR18.PDF
U23 = TPD3S014D_SOT23-6: IC ESD PROTECTION FOR AUTO USB PORT WITH CURRENT LIMIT SWITCH SOT23-6; Chkd/date: MANIRAJA/180918; Crtd /date: ALVY/180918; Custom_Duty: 15%; Customs_HS_Code: 85423100; Distributor_name: DIGIKEY; Distributor_part_number: 296-44163-1-ND; Footprint Path: Y:\MIS_DATABASE\Library\ALTIUM_TOOL\PCB_FOOTPRINTS\Altium_Footprint_Lib.PcbLib; Height: 1.45MM; Library Path: Y:\MIS_DATABASE\Library\ALTIUM_TOOL\SCHEMATICS_PARTS\MS_MISCINTERFACE_Library.schlib; Mfr_name: TEXAS INSTRUMENTS; Mfr_part_number: TPD3S014TDBVRQ1; Mistral Part No: 141018090014-R; Package: SOT23-6; Part_type: ICS\INTERFACE; Project: TI_J7ES_EVM_CP; RoHS: RoHS; Temperature: -40°C+105°C; Tolerance: NA; Voltage: NA; Wattage: NA; Weight: NA; Datasheet: Y:\MIS_DATABASE\DATASHEETS\ICS\INTERFACE\TPD3S014-Q1.PDF
C532 = CAP_POL: CAP TANTALUM 150uF 20V 10% ESR 0.5E X7343; Chkd/date: PRAVEEN/291122; Crtd /date: PRAVEEN/291122; Custom_Duty: 15%; Customs_HS_Code: 85322990; Distributor_name: DIGIKEY; Distributor_part_number: 399-4794-1-ND; Footprint Path: Y:\MIS_DATABASE\Library\ALTIUM_TOOL\PCB_FOOTPRINTS\Altium_Footprint_Lib.PcbLib; Height: 4.30MM; Library Path: Y:\MIS_DATABASE\Library\ALTIUM_TOOL\SCHEMATICS_PARTS\MS_DISCRETE_Library.schlib; Mfr_name: KEMET; Mfr_part_number: T491X157K020AT; Mistral Part No: 120022110050-R; Package: X7343; Part_type: CAPACITORS\TANTALUM; Project: SK-AM62Q-LP_EVM; RoHS: RoHS; Temperature: -55°C+125°C; Tolerance: 10%; Voltage: 20V; Wattage: NA; Weight: 600mg; Datasheet: Y:\MIS_DATABASE\DATASHEETS\CAPACITORS\KEMET_T491_MAR18.PDF
D6 D11 = DIODE_TVS_DUAL: DIODE 1CH ESD PROTECTION FOR USB TYPE-C AND THUNDERBOLT3 X2SON2; Chkd/date: MANIRAJA/230920; Crtd /date: ALVY/230920; Custom_Duty: 15%; Customs_HS_Code: 85412900; Distributor_name: DIGIKEY; Distributor_part_number: 296-44484-1-ND; Footprint Path: Y:\MIS_DATABASE\Library\ALTIUM_TOOL\PCB_FOOTPRINTS\Altium_Footprint_Lib.PcbLib; Height: 0.32MM; Library Path: Y:\MIS_DATABASE\Library\ALTIUM_TOOL\SCHEMATICS_PARTS\MS_DISCRETE_Library.schlib; Mfr_name: TEXAS INSTRUMENTS; Mistral Part No: 130020090037-R; Package: X2SON2; Part_type: DIODE\TVS; Project: AM64X_SKEVM; RoHS: RoHS; Temperature: -40°C+125°C; Tolerance: NA; Voltage: NA; Wattage: NA; Weight: 0.2mg; Datasheet: Y:\MIS_DATABASE\DATASHEETS\DISCRETES\DIODES\TPD1E01B04.PDF
D7 = DIODE_ESD122DMXR: DIODE 2-CH ESD PROTECTION FOR USB TYPE-C AND HDMI 2.0 X2SON-3; Chkd/date: MANIRAJA/140817; Crtd /date: MANIRAJA/140817; Custom_Duty: 15%; Customs_HS_Code: 85412900; Distributor_name: DIGIKEY; Distributor_part_number: ESD122DMXR-ND; Height: 0.40MM; Mfr_name: TEXAS INSTRUMENTS; Mistral Part No: 130017080015-R; Package: X2SON-3; Part_type: DIODE\TVS; Project: TI_SVB_CONTROLLER CARD; RoHS: RoHS; Temperature: -40°C+125°C; Tolerance: NA; Voltage: NA; Wattage: NA; Weight: NA; Datasheet: Y:\MIS_DATABASE\DATASHEETS\DISCRETES\DIODES\ESD122XX.PDF
J15 = CON_USB-C_24_1240183621: CON USB-C TYPE 24POS FEMALE RT SMD; Chkd/date: MANIRAJA/050618; Crtd /date: ALVY/040618; Custom_Duty: 24%; Customs_HS_Code: 85369090; Distributor_name: DIGIKEY; Distributor_part_number: WM17992CT-ND; Footprint Path: Y:\MIS_DATABASE\Library\ALTIUM_TOOL\PCB_FOOTPRINTS\Altium_Footprint_Lib.PcbLib; Height: 3.86MM; Library Path: Y:\MIS_DATABASE\Library\ALTIUM_TOOL\SCHEMATICS_PARTS\MS_CONNECTOR_Library.schlib; Mfr_name: MOLEX; Mfr_part_number: 2012670005; Mistral Part No: 150018060002-R; Package: SMD; Part_type: CONNECTOR\USB; Project: TI_J7SVB_USB_ADD-ON-CARD; RoHS: RoHS; Temperature: -40°C+105°C; Tolerance: NA; Voltage: NA; Wattage: NA; Weight: 0.686g; Datasheet: Y:\MIS_DATABASE\DATASHEETS\CONNECTORS\2012670X.PDF
LD5 LD6 LD9 = DIODE_LED: DIODE LED BRIGHT GREEN SMD; Chkd/date: MANIRAJA/180820; Crtd /date: ALVY/180820; Custom_Duty: 24%; Customs_HS_Code: 85439000; Distributor_name: DIGIKEY; Distributor_part_number: 732-4986-1-ND; Footprint Path: Y:\MIS_DATABASE\Library\ALTIUM_TOOL\PCB_FOOTPRINTS\Altium_Footprint_Lib.PcbLib; Height: 0.80MM; Library Path: Y:\MIS_DATABASE\Library\ALTIUM_TOOL\SCHEMATICS_PARTS\MS_OPTO_Library.schlib; Mfr_name: WURTH ELECTRONICS; Mistral Part No: 130020080012-R; Package: SMD; Part_type: OPTO\LED; Project: AM64x_EVM_BRD; RoHS: RoHS; Temperature: -40°C+85°C; Tolerance: NA; Voltage: NA; Wattage: NA; Weight: 10mg; Datasheet: Y:\MIS_DATABASE\DATASHEETS\DISCRETES\LEDS\150080VS75000.PDF
Q8 = NPN_BEC: TRANSISTOR NPN SOT23-3; Alternate_mfr_name_A: FAIRCHILD SEMICONDUCTOR; Alternate_mfr_name_B: PHILIPS; Alternate_mfr_name_C: ZETEX; Alternate_mfr_name_D: ST MICROELECTRONICS / PHILIPS SEMICONDUCTORS; Alternate_mfr_part_number_A: BC846B; Alternate_mfr_part_number_C: FMMT2369; Alternate_mfr_part_number_D: MMBT3904; Chkd/date: SHREESHAIL/020206; Crtd /date: MAZHAR/140505; Custom_Duty: 15%; Customs_HS_Code: 85412900; Distributor_name: DIGIKEY; Distributor_part_number: 568-1631-1-ND; Height: 1.14MM; Manufacturer: FAIRCHILD; Mfr_name: FAIRCHILD; Mfr_part_number: BC817-40; Mistral Part No: 130009031166-R; Package: SOT23-3; Part_type: TRANSISTOR\BIPOLAR; Project: G4_SVGA; RoHS: RoHS; Temperature: -65°C+150°C; Datasheet: Y:\MIS_DATABASE\DATASHEETS\DISCRETES\TRANSISTORS_FETS\BC817.PDF
Q14 Q15 = MOSFET_CSD17313Q2: IC MOSFET N-CHANNEL NEXFET 25V WSON6; Chkd/date: ALVY/071220; Crtd /date: MANIRAJA/071220; Custom_Duty: 15%; Customs_HS_Code: 85423100; Distributor_name: DIGIKEY; Distributor_part_number: 296-25260-1-ND; Footprint Path: Y:\MIS_DATABASE\Library\ALTIUM_TOOL\PCB_FOOTPRINTS\Altium_Footprint_Lib.PcbLib; Height: 0.80MM; Library Path: Y:\MIS_DATABASE\Library\ALTIUM_TOOL\SCHEMATICS_PARTS\MS_MOSFET_Library.schlib; Manufacturer: TEXAS INSTRUMENTS; Mfr_name: TEXAS INSTRUMENTS; Mistral Part No: 142020120008-R; Package: WSON6; Part_type: ICS\POWER\MOSFET; Project: TI_AM243x LP EVM; RoHS: RoHS; Temperature: -55°C+150°C; Tolerance: NA; Voltage: NA; Wattage: NA; Weight: 8.7mg; Datasheet: Y:\MIS_DATABASE\DATASHEETS\ICS\POWER\CSD16301Q2.PDF
R139 R155 = RESISTOR: RES 220E 1/10W 5% 0402; Chkd/date: VASANTHA/291216; Crtd /date: GEETHA/260406; Custom_Duty: 15%; Customs_HS_Code: 85332119; Distributor_name: DIGIKEY; Distributor_part_number: P220JCT-ND; Footprint Path: Y:\MIS_DATABASE\Library\ALTIUM_TOOL\PCB_FOOTPRINTS\Altium_Footprint_Lib.PcbLib; Height: 0.40MM; Library Path: Y:\MIS_DATABASE\Library\ALTIUM_TOOL\SCHEMATICS_PARTS\MS_DISCRETE_Library.schlib; Mfr_name: PANASONIC-ECG; Mfr_part_number: ERJ-2GEJ221X; Mistral Part No: 110009030506-R; Package: 0402; Part_type: RESISTORS\FIXED; Project: RED EYE; RoHS: RoHS; Temperature: -55°C+155°C; Tolerance: 5%; Voltage: NA; Wattage: 1/10W; Weight: 0.8mg; Datasheet: Y:\MIS_DATABASE\DATASHEETS\RESISTORS\PAN-ERJSER_NOV17.PDF
R214 R406 = RESISTOR: RES 1K 1/10W 1% 0402; Chkd/date: VASANTHA/281216; Crtd /date: MAZHAR/150506; Custom_Duty: 15%; Customs_HS_Code: 85332119; Distributor_name: DIGIKEY; Distributor_part_number: P1.00KLCT-ND; Footprint Path: Y:\MIS_DATABASE\Library\ALTIUM_TOOL\PCB_FOOTPRINTS\Altium_Footprint_Lib.PcbLib; Height: 0.40MM; Library Path: Y:\MIS_DATABASE\Library\ALTIUM_TOOL\SCHEMATICS_PARTS\MS_DISCRETE_Library.schlib; Mfr_name: PANASONIC-ECG; Mfr_part_number: ERJ-2RKF1001X; Mistral Part No: 110009030411-R; Package: 0402; Part_type: RESISTORS\FIXED; Project: VOCERA; RoHS: RoHS; Temperature: -55°C+155°C; Tolerance: 1%; Voltage: NA; Wattage: 1/10W; Weight: 0.8mg; Datasheet: Y:\MIS_DATABASE\DATASHEETS\RESISTORS\PAN-ERJSER_NOV17.PDF
R592 = RESISTOR: RES 1K 1/20W 1% 0201; Assembly_Instruction: DNI; Chkd/date: JEBRAN/110815; Crtd /date: JEBRAN/110815; Custom_Duty: 15%; Customs_HS_Code: 85332119; Distributor_name: DIGIKEY; Distributor_part_number: 541-1.00KAABCT-ND; Footprint Path: Y:\MIS_DATABASE\Library\ALTIUM_TOOL\PCB_FOOTPRINTS\Altium_Footprint_Lib.PcbLib; Height: 0.28MM; Library Path: Y:\MIS_DATABASE\Library\ALTIUM_TOOL\SCHEMATICS_PARTS\MS_DISCRETE_Library.schlib; Mfr_name: VISHAY; Mfr_part_number: CRCW02011K00FKED; Mistral Part No: 110015080014-R; Package: 0201; Part_type: RESISTORS\FIXED; Project: OCTASIC_3000; RoHS: RoHS; Temperature: -55°C+155°C; Tolerance: 1%; Voltage: NA; Wattage: 1/20W; Weight: 0.17mg; Datasheet: Y:\MIS_DATABASE\DATASHEETS\RESISTORS\CRCW0201.PDF
U77 = TVS2200_WSON6: IC 22V FLAT-CLAMP SURGE PROTECTION DEVICE WSON6; Chkd/date: MANIRAJA/011021; Crtd /date: ALVY/011021; Custom_Duty: 15%; Customs_HS_Code: 85423100; Distributor_name: DIGIKEY; Distributor_part_number: 296-52187-1-ND; Footprint Path: Y:\MIS_DATABASE\Library\ALTIUM_TOOL\PCB_FOOTPRINTS\Altium_Footprint_Lib.PcbLib; Height: 0.80MM; Library Path: Y:\MIS_DATABASE\Library\ALTIUM_TOOL\SCHEMATICS_PARTS\MS_MISCPOWER_Library.schlib; Mfr_name: TEXAS INSTRUMENTS; Mistral Part No: 142021100001-R; Package: WSON6; Part_type: ICS\POWER; Project: TI_AM62x SKEVM_BRD; RoHS: RoHS; Temperature: -40°C+125°C; Tolerance: NA; Voltage: NA; Wattage: NA; Weight: 12mg; Datasheet: Y:\MIS_DATABASE\DATASHEETS\ICS\POWER\TVS2200.PDF

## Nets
DGND: C41.1 C43.1 C73.2 C81.1 C109.2 C110.2 C111.2 C113.1 C375.2 C376.2 C377.1 C378.2 C416.2 D2.1(A) D3.1(A) D6.2(ANODE) D7.1(GND) D11.2(ANODE) J9.4(GND) J10.2 J10.3 J10.7 J10.9 J10.14 J10.15 J10.20 J10.27 J15.A1(GND) J15.A12(GND) J15.B1(GND) J15.B12(GND) LD6.1(CATHODE) LD9.1(CATHODE) Q8.2(EMITTER) Q14.4(S1) Q14.7(S2) Q15.4(S1) Q15.7(S2) R66.1 R120.2 R131.2 R140.2 R142.1 R143.2 R201.2 R361.2 R366.2 R417.2 U19.4(GND) U23.2(GND) U26.8(GND) U77.1(GND) U77.2(GND) U77.3(GND) U77.7(GND) Y1.2 Y1.4 ; also on sheet 1 2 3 4 13 14 15 16 17 18 19 20 21 22 23 24 25 26 27 28 29 30 31 32 33 37 38 39 40 41 42 43
VBUS_5V0_TYPEA1: C110.1 C375.1 J9.1(VCC) R119.2 U23.4(OUT)
VBUS_TYPEC2: C532.1 J15.A4(VBUS1) J15.A9(VBUS2) J15.B4(VBUS3) J15.B9(VBUS4) R147.2 R214.1 R593.2 U77.4(IN1) U77.5(IN2) U77.6(IN3) ; also on sheet 13
VCC1V8_SYS: C73.1 R116.1 U19.1(VCCA) ; also on sheet 4 16 19 20 22 25 37 39 40 42
VCC_3V3_SYS: C81.2 C113.2 C377.2 C378.1 J10.1 R139.2 R155.2 R402.2 R416.1 R418.2 R419.1 R472.2 U19.8(VCCB) U26.16(VCC) ; also on sheet 1 4 15 16 19 20 21 23 24 26 27 29 30 31 32 33 37 38 39 40 41 42 43
VCC_5V0: C109.1 C111.1 U23.3(IN) ; also on sheet 13 14 33 38 41
VDDR_CORE: R406.1 ; also on sheet 16 17 18
BT_EN_SOC: U12.E7(MCU_SPI0_CS0) ; also on sheet 19
CAN_FD_WKUP_HDR_INH: J10.5 ; also on sheet 32
CONN_MCU_PORz: J10.28 R472.1 ; also on sheet 42
CONN_MCU_RESETz: J10.25 R418.1 ; also on sheet 43
ETH_CAN_INH_SOC: R585.1 ; also on sheet 32
EXP_GPIO0_14: U19.7(B1) ; also on sheet 33
EXP_GPIO0_14_LT: U19.2(A1) ; also on sheet 22
MCU_GPIO0_15: J10.10 R584.2
MCU_GPIO0_15_R: R584.1 R585.2 U12.D5(MCU_MCAN1_TX)
MCU_GPIO0_16: J10.11 U12.D6(MCU_MCAN1_RX)
MCU_I2C0_SCL: J10.24 R416.2 U12.B9(MCU_I2C0_SCL)
MCU_I2C0_SDA: J10.21 R419.2 U12.A10(MCU_I2C0_SDA)
MCU_MCAN0_RX: J10.22 U12.C4(MCU_MCAN0_RX)
MCU_MCAN0_TX: J10.16 U12.C5(MCU_MCAN0_TX)
MCU_OSC0_XI: R70.2 R71.2 U12.A5(MCU_OSC0_XI)
MCU_OSC0_XO: R65.2 R66.2 U12.A6(MCU_OSC0_XO)
MCU_RESETSTATz: J10.23 TP20.1(TP) ; also on sheet 32 42
MCU_SAFETY_ERRORz_1V8: TP36.1(TP) U19.3(A2) ; also on sheet 42
MCU_SAFETY_ERRORz_3V3: J10.26 U19.6(B2)
MCU_SPI0_CLK: J10.18 U12.B7(MCU_SPI0_CLK)
MCU_SPI0_CS1: J10.8 U12.C8(MCU_SPI0_CS1)
MCU_SPI0_D0: J10.6 U12.E8(MCU_SPI0_D0)
MCU_SPI0_D1: J10.4 U12.D8(MCU_SPI0_D1)
MCU_UART0_CTS: U12.B8(MCU_UART0_CTSN) U26.9(3A)
MCU_UART0_CTS_3V3: U26.11(3B1) ; also on sheet 31
MCU_UART0_CTS_CONN: J10.12 U26.10(3B2)
MCU_UART0_MUX_OE: R140.1 U26.15(~{OE})
MCU_UART0_MUX_SEL: J8.2 R142.2 U26.1(S)
MCU_UART0_RTS: U12.D7(MCU_UART0_RTSN) U26.12(4A)
MCU_UART0_RTS_3V3: U26.14(4B1) ; also on sheet 31
MCU_UART0_RTS_CONN: J10.17 U26.13(4B2)
MCU_UART0_RX_3V3: U26.2(1B1) ; also on sheet 31
MCU_UART0_RXD: U12.A8(MCU_UART0_RXD) U26.4(1A)
MCU_UART0_RXD_CONN: J10.13 U26.3(1B2)
MCU_UART0_TX_3V3: U26.5(2B1) ; also on sheet 31
MCU_UART0_TXD: U12.B6(MCU_UART0_TXD) U26.7(2A)
MCU_UART0_TXD_CONN: J10.19 U26.6(2B2)
SoC_CLKIN: R71.1 ; also on sheet 25
SoC_USB0_DM: L5.4(OUT2) U12.AA11(USB0_DM)
SoC_USB0_DP: L5.1(IN1) U12.Y10(USB0_DP)
SoC_USB0_DRVVBUS: R592.1 U12.D17(USB0_DRVVBUS) ; also on sheet 13
SoC_USB0_RCALIB: R366.1 U12.T8(USB0_RCALIB)
SoC_USB0_VBUS: R143.1 R145.1 U12.V10(USB0_VBUS)
SoC_USB1_DM: L4.1(IN1) U12.W8(USB1_DM)
SoC_USB1_DP: L4.4(OUT2) U12.W9(USB1_DP)
SoC_USB1_DRVVBUS: R131.1 R132.1 U12.E16(USB1_DRVVBUS)
SoC_USB1_RCALIB: R361.1 U12.V9(USB1_RCALIB)
SoC_USB1_VBUS: R118.1 R120.1 U12.U9(USB1_VBUS)
USB_TYPEA_EARTH: C376.1 J9.SH1 J9.SH2 R417.1
USB_TYPEACONN1_DM: J9.2(D-) L4.2(IN2) U23.5(D1)
USB_TYPEACONN1_DP: J9.3(D+) L4.3(OUT1) U23.6(D2)
USB_TYPEC2_EARTH: C416.1 J15.SH1 J15.SH2 J15.SH3 J15.SH4 R201.1
USBC_CONN2_CC1: D6.1(CATHODE) J15.A5(CC1) ; also on sheet 13
USBC_CONN2_CC2: D11.1(CATHODE) J15.B5(CC2) ; also on sheet 13
USBC_CONN2_DM: D7.3(IO2) J15.A7(D-_1) J15.B7(D-_2) L5.3(OUT1)
USBC_CONN2_DP: D7.2(IO1) J15.A6(D+_1) J15.B6(D+_2) L5.2(IN2)
N16906426: C43.2 R70.1 Y1.1
N16906432: C41.2 R65.1 Y1.3
N17031262: LD9.2(ANODE) R214.2
N17492093: R116.2 U19.5(OE)
N17492111: J8.1 R402.1
N17726648: D3.3(C) R145.2 R147.1
N20199452: D2.3(C) R118.2 R119.1
N21030238: LD6.2(ANODE) R155.1
N21068099: R132.2 U23.1(EN)
N21117349: LD5.1(CATHODE) Q8.3(COLLECTOR)
N21117357: LD5.2(ANODE) R139.1
N21117537: Q8.1(BASE) R406.2
N22221349: Q15.3(G) R592.2
N22221705: C532.2 Q14.1(D1) Q14.2(D2) Q14.5(D3) Q14.6(D4) Q14.8(D5)
N22234960: Q15.1(D1) Q15.2(D2) Q15.5(D3) Q15.6(D4) Q15.8(D5) R593.1 R594.1
N22235133: Q14.3(G) R594.2

Not connected (* = marked no-connect by the designer): D2 2(NC)*; D3 2(NC)*; J15 A2(TX1+)* A3(TX1-)* A8(SBU1)* A10(RX2-)* A11(RX2+)* B2(TX2+)* B3(TX2-)* B8(SBU2)* B10(RX1-)* B11(RX1+)*

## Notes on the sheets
sheet 34
- D-Note :-
  A pullup is recommended for Open drain output type
  I2C interfaces irrespective of the IO configuration
  Refer pin connectivity table of SOC data sheet
- D-Note :-
  Open-drain output type buffer I2C interfaces
  have slew rate requirement when pulled  to 3.3 V
  An RC is recommended for slew rate control
  Refer SK-AM62P-LP schematics
- D-Note :-
  SOC IO buffers are off during
  reset. A pull is recommended near
  to the attached device that is
  being driven by the SOC IO
- SOC - MCU DOMAIN
- D-Note :-
  Add a series resistor 22R to the SPI0
  clock output near to the SoC
- D-Note :-
  No HFOSC0 registers are required to be changed. These registers should remain in their
  default state.
  Select the appropriate crystal circuit components that are compliant to the values
  defined in the MCU_OSC0 Crystal Circuit Requirements table.
  Read the Load Capacitance and Shunt Capacitance sections to select the appropriate
  crystal circuit components.
- D-Note :-
  Refer Applications, Implementation, and Layout section of
  the data sheet  for clock routing guidelines as below:
  Clock Routing Guidelines
  Oscillator Routing
- D-Note :-
  MCU_OSC0  has been validated only with a 25 MHz clock source, so that is the only
  frequency supported.
  The datasheet shows MCU_OSC0 not starting until after the core voltage because there
  are some cases where the oscillator may not start until VDD_CORE is valid. In most
  cases it will start as early as VDDS_OSC0, but this may not always be the case.
  This diagram in the datasheet is showing the maximum start-up time, which must include
  the case where the delay is based on VDD_CORE being valid.
- D-Note :-
  Connect the 25 MHz crystal directly to the SOC Xi and Xo pins
  (No Series or parallel resistors are recommended).
  The internal oscillator implements AGC (Automatic Gain Control)
  for amplitude control
  Match the SOC and the EPHY crystal specs
- D-Note :-
  XO should be grounded when
  external oscillator is used
  Refer SOC data sheet
- SOC-MCU HEADER
- D-Note :-
  Any SoC IO that has a trace connected
  but not being driven actively needs to
  be connected to an external pull.
  When adding pull is not feasible, ensure
  the traces are routed away from noisy
  signals
- SOC - MCU_UART0 MUX
- Silk: MCU HDR
- INPUT/OUTPUT
- OEn
- SEL
- An
- L
- L(DEFAULT)
- An=nB1
- SOC - FT4232
- L
- H
- An=nB2
- SOC - MCU HEADER
sheet 35
- USB1 - USB 2.0 TYPE-A
- D-Note :-
  Use power switch with OC indication
  Example TPS2051
  Connect OC output of the power switch to
  SoC IO for USB VBUS over load detection
  Refer SK-AM62P-LP schematics
- 90E
- To Type- C connector
  Port: 2 of PD Controller
- 90E
- To Type- A connector
- D-Note :-
  DNI USBx_DRVVBUS pullup
  and pulldown to implement
  wakeup from deep sleep.
  For Normal USB operation,
  there is an internal
  pulldown enabled during
  SOC reset
- CAD Note :-
  Place pulldown near to EN pin -
  pin 1 of USB power switch
- 90E
- DLW21SZ900HQ2B
- Silk: TYPE-A
- D-Note :-
  Provide provision to bypass
  the CMC using 0R resistor
  for performance testing
- D-Note:- Refer USB VBUS Design Guidelines section of SoC data sheet
- D-Note:- VBUS connection is optional for Host configuration
sheet 36
- USB 2.0 TYPE-C DRP
- Silk: TYPE-C DRP
- 90E
- DLW21SZ900HQ2B
- D-Note
  Provide provision to bypass the CMC using
  0R resistor for performance testing
- MOSFET SWITCH FOR ADDITIONAL CAPACITANCE
- POWER INDICATION LED: VBUS_TYPEC2
- POWER RAIL LEDS
- D-Note
  Ok to use a 1K
  standard 5% tolerance
  resistor
- R-Note :-
  This is a supply negotiation
  indicator.
  On indicates success.
